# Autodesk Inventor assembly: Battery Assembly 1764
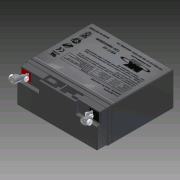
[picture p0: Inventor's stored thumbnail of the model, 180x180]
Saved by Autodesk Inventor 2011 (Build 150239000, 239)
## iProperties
Created: 2008-01
Part Number: Battery Assembly 1764
Document SubType Name: Assembly
Designer: rlindsay
Author: rlindsay
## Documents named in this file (7)
- R:\CAD Archives\Battery\Battery 1764\Battery Assembly 1764.iam
- R:\CAD Archives\Battery\Battery 1764\main body 1764.ipt
- R:\CAD Archives\Battery\Battery 1764\battery 1764.ipt
- R:\CAD Archives\Battery\Battery 1764\Battery Screw 1764.ipt
- R:\CAD Archives\Battery\Battery 1764\Battery Nut 1764.ipt
- R:\CAD Archives\Battery\Battery 1764\Battery Screw 2 1764.ipt
- R:\CAD Archives\Battery\Battery 1764\Battery Clip 1764.ipt
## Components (11 placed, 6 different names)
1. Battery Screw 1764:1 — Mate:14, Mate:15, Mate:16
2. Battery Clip 1764:1 — Mate:7, Mate:8, Flush:2
3. Battery Clip 1764:2 — Mate:5, Mate:6, Flush:1
4. Battery Screw 1764:2 — Mate:13, Mate:18, Mate:19
5. main body 1764:1 — Mate:1, Mate:2, Mate:5, Mate:6, Flush:1, Mate:9, Mate:10, Mate:15
6. main body 1764:2 — Mate:3, Mate:4, Mate:7, Mate:8, Flush:2, Mate:11, Mate:12, Mate:20
7. Battery Nut 1764:1 — Mate:14, Mate:17
8. Battery Nut 1764:2 — Mate:13, Mate:20
9. Battery Screw 2 1764:1 — Mate:11, Mate:12
10. Battery Screw 2 1764:2 — Mate:9, Mate:10
11. battery 1764:1 — Mate:1, Mate:2, Mate:3, Mate:4, Mate:16, Mate:17, Mate:18, Mate:19
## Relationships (22: Mate 20, Flush 2)
- Mate:1: main body 1764:1 ↔ battery 1764:1
- Mate:2: main body 1764:1 ↔ battery 1764:1
- Mate:3: main body 1764:2 ↔ battery 1764:1
- Mate:4: main body 1764:2 ↔ battery 1764:1
- Mate:5: Battery Clip 1764:2 ↔ main body 1764:1
- Mate:6: Battery Clip 1764:2 ↔ main body 1764:1
- Flush:1: Battery Clip 1764:2 ↔ main body 1764:1
- Mate:7: Battery Clip 1764:1 ↔ main body 1764:2
- Mate:8: Battery Clip 1764:1 ↔ main body 1764:2
- Flush:2: Battery Clip 1764:1 ↔ main body 1764:2
- Mate:9: main body 1764:1 ↔ Battery Screw 2 1764:2
- Mate:10: main body 1764:1 ↔ Battery Screw 2 1764:2
- Mate:11: main body 1764:2 ↔ Battery Screw 2 1764:1
- Mate:12: main body 1764:2 ↔ Battery Screw 2 1764:1
- Mate:13: Battery Screw 1764:2 ↔ Battery Nut 1764:2
- Mate:14: Battery Screw 1764:1 ↔ Battery Nut 1764:1
- Mate:15: Battery Screw 1764:1 ↔ main body 1764:1
- Mate:16: Battery Screw 1764:1 ↔ battery 1764:1
- Mate:17: Battery Nut 1764:1 ↔ battery 1764:1
- Mate:18: Battery Screw 1764:2 ↔ battery 1764:1
- Mate:19: Battery Screw 1764:2 ↔ battery 1764:1
- Mate:20: main body 1764:2 ↔ Battery Nut 1764:2
